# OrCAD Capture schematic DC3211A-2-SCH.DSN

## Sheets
1 PAGE2: size Custom
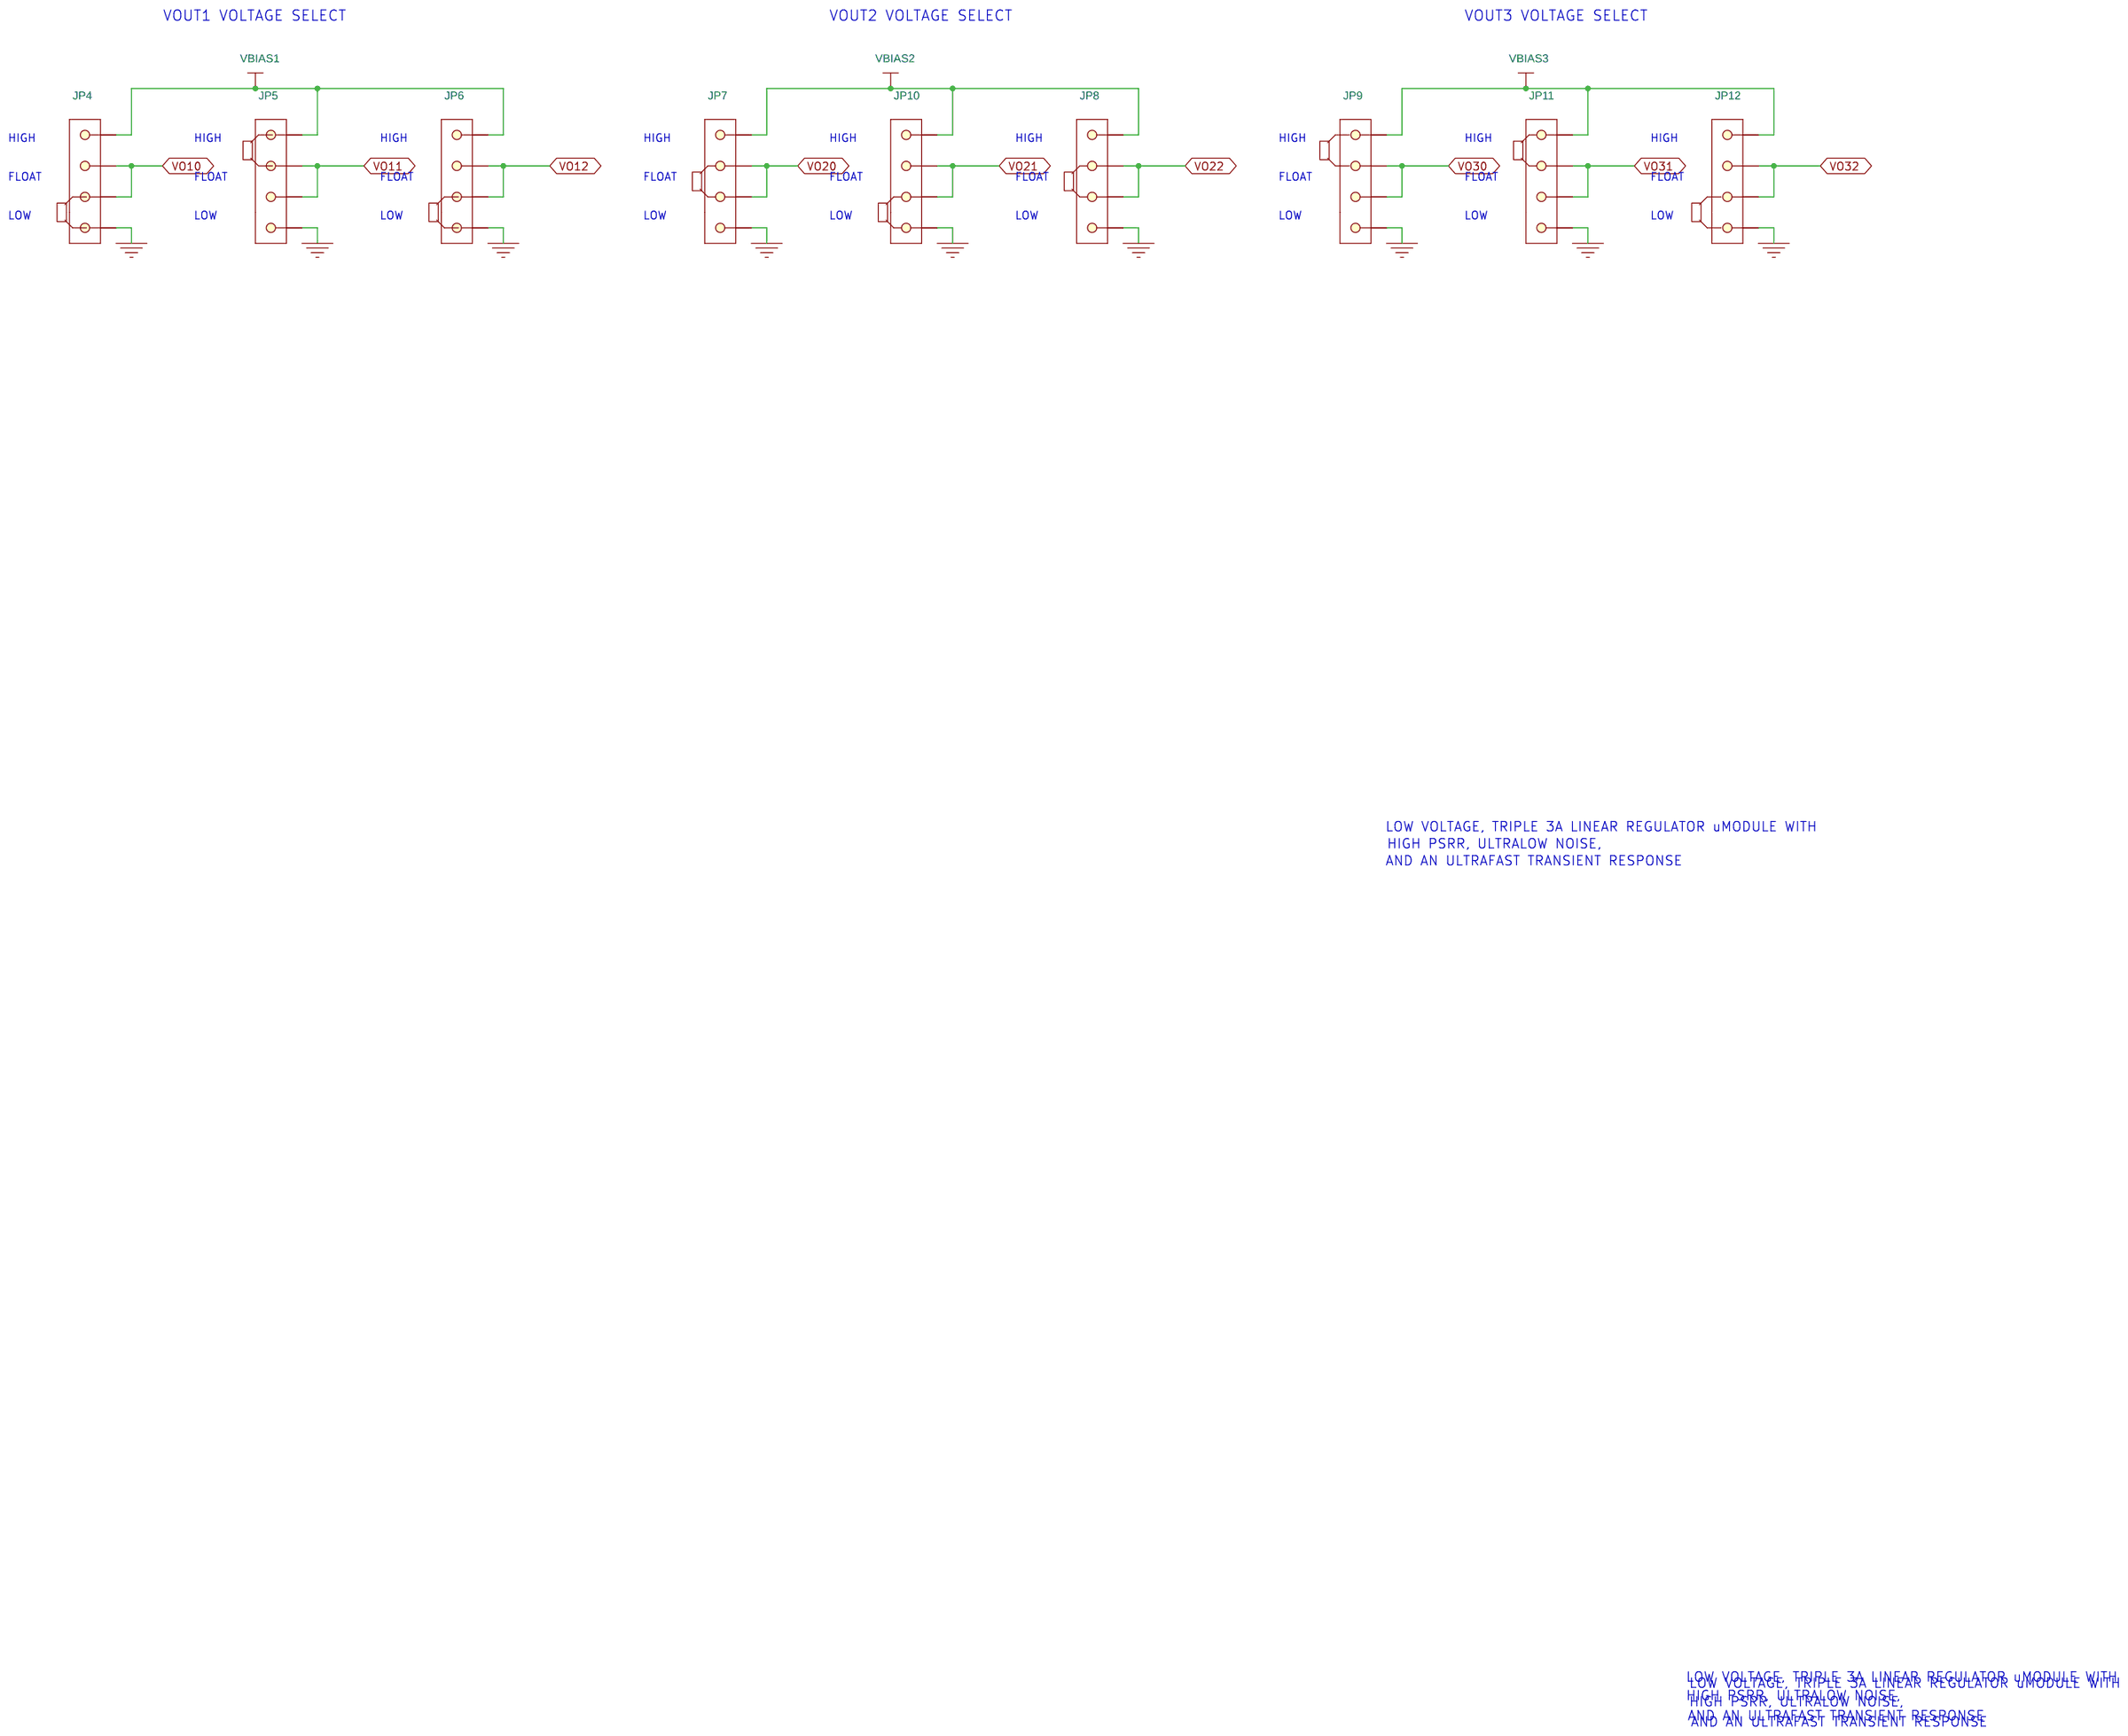
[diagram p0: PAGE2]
2 PAGE1: size Custom
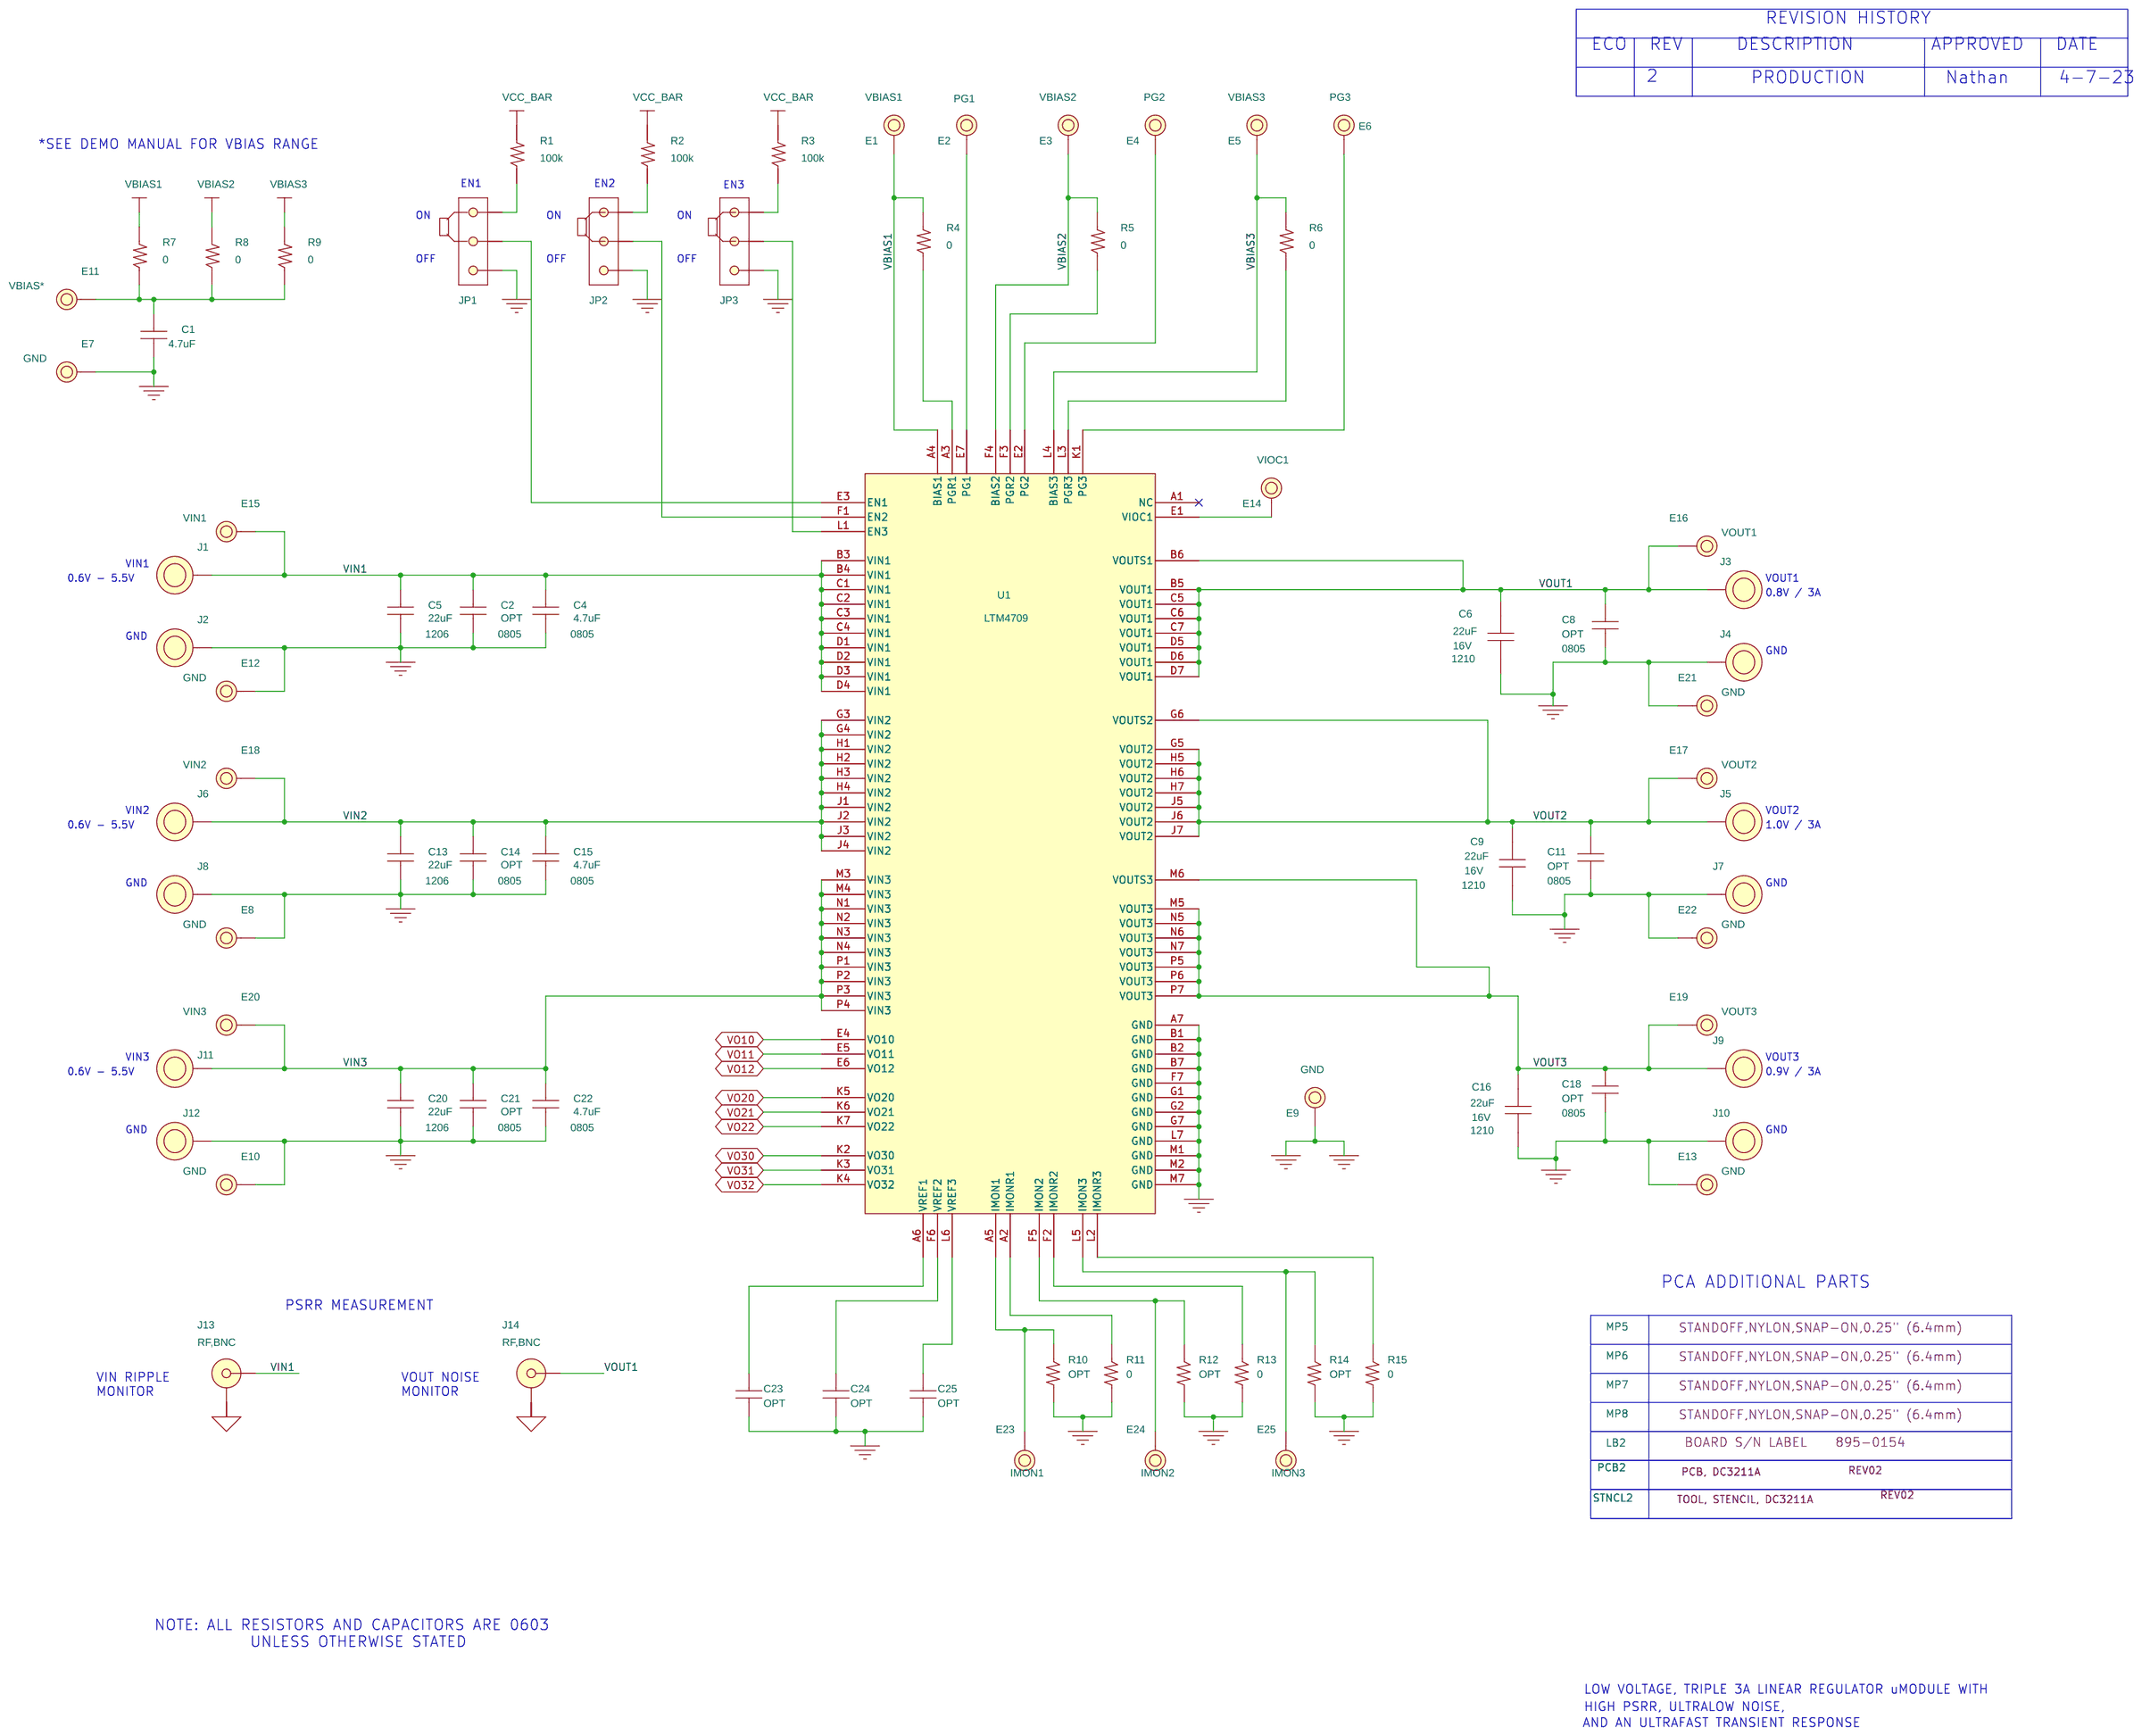
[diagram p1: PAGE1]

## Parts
sheet PAGE1
C1  4.7uF  [CC0603N]
C2  OPT  [CC0805N]
C4  4.7uF  [CC0805N]
C5  22uF  [CC1206N]
C6  22uF  [1210-SP]
C8  OPT  [CC0805N]
C9  22uF  [1210-SP]
C11  OPT  [CC0805N]
C13  22uF  [CC1206N]
C14  OPT  [CC0805N]
C15  4.7uF  [CC0805N]
C16  22uF  [1210-SP]
C18  OPT  [CC0805N]
C20  22uF  [CC1206N]
C21  OPT  [CC0805N]
C22  4.7uF  [CC0805N]
C23  OPT  [CC0603N]
C24  OPT  [CC0603N]
C25  OPT  [CC0603N]
E1  TEST POINT  [MILLMAX2501]
E2  TEST POINT  [MILLMAX2501]
E3  TEST POINT  [MILLMAX2501]
E4  TEST POINT  [MILLMAX2501]
E5  TEST POINT  [MILLMAX2501]
E6  TEST POINT  [MILLMAX2501]
E7  TEST POINT  [MILLMAX2501]
E8  TEST POINT  [MILLMAX2501]
E9  TEST POINT  [MILLMAX2501]
E10  TEST POINT  [MILLMAX2501]
E11  TEST POINT  [MILLMAX2501]
E12  TEST POINT  [MILLMAX2501]
E13  TEST POINT  [MILLMAX2501]
E14  TEST POINT  [MILLMAX2501]
E15  TEST POINT  [MILLMAX2501]
E16  TEST POINT  [MILLMAX2501]
E17  TEST POINT  [MILLMAX2501]
E18  TEST POINT  [MILLMAX2501]
E19  TEST POINT  [MILLMAX2501]
E20  TEST POINT  [MILLMAX2501]
E21  TEST POINT  [MILLMAX2501]
E22  TEST POINT  [MILLMAX2501]
E23  TEST POINT  [MILLMAX2501]
E24  TEST POINT  [MILLMAX2501]
E25  TEST POINT  [MILLMAX2501]
J1  BANANA JACK  [KEY-575-4]
J2  BANANA JACK  [KEY-575-4]
J3  BANANA JACK  [KEY-575-4]
J4  BANANA JACK  [KEY-575-4]
J5  BANANA JACK  [KEY-575-4]
J6  BANANA JACK  [KEY-575-4]
J7  BANANA JACK  [KEY-575-4]
J8  BANANA JACK  [KEY-575-4]
J9  BANANA JACK  [KEY-575-4]
J10  BANANA JACK  [KEY-575-4]
J11  BANANA JACK  [KEY-575-4]
J12  BANANA JACK  [KEY-575-4]
J13  RF,BNC  [CONNEX-112404]
J14  RF,BNC  [CONNEX-112404]
JP1  HDR.  [HD1X3-079]
JP2  HDR.  [HD1X3-079]
JP3  HDR.  [HD1X3-079]
LB2  LABEL  [895-0154_REV01]
MP5  STANDOFF  [MTG-8831]
MP6  STANDOFF  [MTG-8831]
MP7  STANDOFF  [MTG-8831]
MP8  STANDOFF  [MTG-8831]
PCB2  PCB, DC3211A
R1  100k  [CR0603N]
R2  100k  [CR0603N]
R3  100k  [CR0603N]
R4  0  [CR0603N]
R5  0  [CR0603N]
R6  0  [CR0603N]
R7  0  [CR0603N]
R8  0  [CR0603N]
R9  0  [CR0603N]
R10  OPT  [CR0603N]
R11  0  [CR0603N]
R12  OPT  [CR0603N]
R13  0  [CR0603N]
R14  OPT  [CR0603N]
R15  0  [CR0603N]
STNCL2  TOOL, STENCIL, DC3211A
U1  LTM4709  [LTM-BGA-98-7090]
XJP1  SHUNT
XJP2  SHUNT
XJP3  SHUNT
sheet PAGE2
JP4  HDR  [HD1X4-079]
JP5  HDR  [HD1X4-079]
JP6  HDR  [HD1X4-079]
JP7  HDR  [HD1X4-079]
JP8  HDR  [HD1X4-079]
JP9  HDR  [HD1X4-079]
JP10  HDR  [HD1X4-079]
JP11  HDR  [HD1X4-079]
JP12  HDR  [HD1X4-079]
XJP4  SHUNT
XJP5  SHUNT
XJP6  SHUNT
XJP7  SHUNT
XJP8  SHUNT
XJP9  SHUNT
XJP10  SHUNT
XJP11  SHUNT
XJP12  SHUNT

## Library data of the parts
C1 = CAP: CAP.,4.7uF,X5R,16V,10%,0603; CLASS: DISCRETE; Dielectric Type: X5R; FPLIST: CC0603N,CC0603L,CC0603M; Inventory Qty: 44050; Manufacturer: MURATA; Manufacturer PN: GRM188R61C475KAAJD; PART_NUMBER: 150-3182; Package Size: 0603; Rated Voltage: 16V; Tolerance: 10%
C2 C8 C11 C14 C18 C21 = CAP: CAP., OPTION, 0805; CLASS: DISCRETE; FPLIST: CC0805N,CC0805L,CC0805M; PART_NUMBER: 150-3036; Package Size: 0805; Package Type: SMD
C4 C15 C22 = CAP: CAP.,4.7uF,X7R,16V,10%,0805; CLASS: DISCRETE; Dielectric Type: X7R; FPLIST: CC0805N,CC0805L,CC0805M; Inventory Qty: 29963; Manufacturer: AVX; Manufacturer PN: 0805YC475KAT2A; PART_NUMBER: 150-0152; Package Size: 0805; Rated Voltage: 16V; Tolerance: 10%
C5 C13 C20 = CAP: CAP.,22uF,X7R,10V,10%,1206; CLASS: DISCRETE; Dielectric Type: X7R; FPLIST: CC1206N,CC1206L,CC1206M; Inventory Qty: 6204; Manufacturer: MURATA; Manufacturer PN: GRM31CR71A226KE15L; PART_NUMBER: 150-2246; Package Size: 1206; Rated Voltage: 10V; Tolerance: 10%
C6 = CAP_1: CAP.,22uF,X7R,16V,10%,1210,NO SUBS. ALLOWED; CLASS: DISCRETE; Dielectric Type: X7R; FPLIST: CC1206N,CC1206L,CC1206M; Inventory Qty: 12345679; Manufacturer: MURATA; Manufacturer PN: GCM32ER71C226KE19L; PART_NUMBER: LOCAL-150-9876; Package Size: 1210; Rated Voltage: 16V; Tolerance: 10%
C9 = CAP_2: CAP.,22uF,X7R,16V,10%,1210,NO SUBS. ALLOWED; CLASS: DISCRETE; Dielectric Type: X7R; FPLIST: CC1206N,CC1206L,CC1206M; Inventory Qty: 12345679; Manufacturer: MURATA; Manufacturer PN: GCM32ER71C226KE19L; PART_NUMBER: LOCAL-150-9876; Package Size: 1210; Rated Voltage: 16V; Tolerance: 10%
C16 = CAP_3: CAP.,22uF,X7R,16V,10%,1210,NO SUBS. ALLOWED; CLASS: DISCRETE; Dielectric Type: X7R; FPLIST: CC1206N,CC1206L,CC1206M; Inventory Qty: 12345679; Manufacturer: MURATA; Manufacturer PN: GCM32ER71C226KE19L; PART_NUMBER: LOCAL-150-9876; Package Size: 1210; Rated Voltage: 16V; Tolerance: 10%
C23-C25 = CAP: CAP., OPTION, 0603; CLASS: DISCRETE; FPLIST: CC0603N,CC0603L,CC0603M; PART_NUMBER: 150-3038; Package Size: 0603; Package Type: SMD
E1 = TESTPOINT_.219_MILL-MAX_2501: TEST POINT,TURRET,0.094" MTG. HOLE,PCB 0.062" THK; CLASS: IO; Inventory Qty: 823526; Manufacturer: MILL-MAX; Manufacturer PN: 2501-2-00-80-00-00-07-0; PART_FIELD_01: VBIAS1; PART_NUMBER: 260-0003
E2 = TESTPOINT_.219_MILL-MAX_2501: TEST POINT,TURRET,0.094" MTG. HOLE,PCB 0.062" THK; CLASS: IO; Inventory Qty: 823526; Manufacturer: MILL-MAX; Manufacturer PN: 2501-2-00-80-00-00-07-0; PART_FIELD_01: PG1; PART_NUMBER: 260-0003
E3 = TESTPOINT_.219_MILL-MAX_2501: TEST POINT,TURRET,0.094" MTG. HOLE,PCB 0.062" THK; CLASS: IO; Inventory Qty: 823526; Manufacturer: MILL-MAX; Manufacturer PN: 2501-2-00-80-00-00-07-0; PART_FIELD_01: VBIAS2; PART_NUMBER: 260-0003
E4 = TESTPOINT_.219_MILL-MAX_2501: TEST POINT,TURRET,0.094" MTG. HOLE,PCB 0.062" THK; CLASS: IO; Inventory Qty: 823526; Manufacturer: MILL-MAX; Manufacturer PN: 2501-2-00-80-00-00-07-0; PART_FIELD_01: PG2; PART_NUMBER: 260-0003
E5 = TESTPOINT_.219_MILL-MAX_2501: TEST POINT,TURRET,0.094" MTG. HOLE,PCB 0.062" THK; CLASS: IO; Inventory Qty: 823526; Manufacturer: MILL-MAX; Manufacturer PN: 2501-2-00-80-00-00-07-0; PART_FIELD_01: VBIAS3; PART_NUMBER: 260-0003
E6 = TESTPOINT_.219_MILL-MAX_2501: TEST POINT,TURRET,0.094" MTG. HOLE,PCB 0.062" THK; CLASS: IO; Inventory Qty: 823526; Manufacturer: MILL-MAX; Manufacturer PN: 2501-2-00-80-00-00-07-0; PART_FIELD_01: PG3; PART_NUMBER: 260-0003
E7-E10 E12 E13 E21 E22 = TESTPOINT_.219_MILL-MAX_2501: TEST POINT,TURRET,0.094" MTG. HOLE,PCB 0.062" THK; CLASS: IO; Inventory Qty: 823526; Manufacturer: MILL-MAX; Manufacturer PN: 2501-2-00-80-00-00-07-0; PART_FIELD_01: GND; PART_NUMBER: 260-0003
E11 = TESTPOINT_.219_MILL-MAX_2501: TEST POINT,TURRET,0.094" MTG. HOLE,PCB 0.062" THK; CLASS: IO; Inventory Qty: 823526; Manufacturer: MILL-MAX; Manufacturer PN: 2501-2-00-80-00-00-07-0; PART_FIELD_01: VBIAS*; PART_NUMBER: 260-0003
E14 = TESTPOINT_.219_MILL-MAX_2501: TEST POINT,TURRET,0.094" MTG. HOLE,PCB 0.062" THK; CLASS: IO; Inventory Qty: 823526; Manufacturer: MILL-MAX; Manufacturer PN: 2501-2-00-80-00-00-07-0; PART_FIELD_01: VIOC1; PART_NUMBER: 260-0003
E15 = TESTPOINT_.219_MILL-MAX_2501: TEST POINT,TURRET,0.094" MTG. HOLE,PCB 0.062" THK; CLASS: IO; Inventory Qty: 823526; Manufacturer: MILL-MAX; Manufacturer PN: 2501-2-00-80-00-00-07-0; PART_FIELD_01: VIN1; PART_NUMBER: 260-0003
E16 = TESTPOINT_.219_MILL-MAX_2501: TEST POINT,TURRET,0.094" MTG. HOLE,PCB 0.062" THK; CLASS: IO; Inventory Qty: 823526; Manufacturer: MILL-MAX; Manufacturer PN: 2501-2-00-80-00-00-07-0; PART_FIELD_01: VOUT1; PART_NUMBER: 260-0003
E17 = TESTPOINT_.219_MILL-MAX_2501: TEST POINT,TURRET,0.094" MTG. HOLE,PCB 0.062" THK; CLASS: IO; Inventory Qty: 823526; Manufacturer: MILL-MAX; Manufacturer PN: 2501-2-00-80-00-00-07-0; PART_FIELD_01: VOUT2; PART_NUMBER: 260-0003
E18 = TESTPOINT_.219_MILL-MAX_2501: TEST POINT,TURRET,0.094" MTG. HOLE,PCB 0.062" THK; CLASS: IO; Inventory Qty: 823526; Manufacturer: MILL-MAX; Manufacturer PN: 2501-2-00-80-00-00-07-0; PART_FIELD_01: VIN2; PART_NUMBER: 260-0003
E19 = TESTPOINT_.219_MILL-MAX_2501: TEST POINT,TURRET,0.094" MTG. HOLE,PCB 0.062" THK; CLASS: IO; Inventory Qty: 823526; Manufacturer: MILL-MAX; Manufacturer PN: 2501-2-00-80-00-00-07-0; PART_FIELD_01: VOUT3; PART_NUMBER: 260-0003
E20 = TESTPOINT_.219_MILL-MAX_2501: TEST POINT,TURRET,0.094" MTG. HOLE,PCB 0.062" THK; CLASS: IO; Inventory Qty: 823526; Manufacturer: MILL-MAX; Manufacturer PN: 2501-2-00-80-00-00-07-0; PART_FIELD_01: VIN3; PART_NUMBER: 260-0003
E23 = TESTPOINT_.219_MILL-MAX_2501: TEST POINT,TURRET,0.094" MTG. HOLE,PCB 0.062" THK; CLASS: IO; Inventory Qty: 823526; Manufacturer: MILL-MAX; Manufacturer PN: 2501-2-00-80-00-00-07-0; PART_FIELD_01: IMON1; PART_NUMBER: 260-0003
E24 = TESTPOINT_.219_MILL-MAX_2501: TEST POINT,TURRET,0.094" MTG. HOLE,PCB 0.062" THK; CLASS: IO; Inventory Qty: 823526; Manufacturer: MILL-MAX; Manufacturer PN: 2501-2-00-80-00-00-07-0; PART_FIELD_01: IMON2; PART_NUMBER: 260-0003
E25 = TESTPOINT_.219_MILL-MAX_2501: TEST POINT,TURRET,0.094" MTG. HOLE,PCB 0.062" THK; CLASS: IO; Inventory Qty: 823526; Manufacturer: MILL-MAX; Manufacturer PN: 2501-2-00-80-00-00-07-0; PART_FIELD_01: IMON3; PART_NUMBER: 260-0003
J1-J12 = BANANA_KEYSTONE-575-4: CONN.,BANANA JACK,FEMALE,THT,NON-INSULATED,SWAGE,0.218"; CLASS: IO; Inventory Qty: 203061; Manufacturer: KEYSTONE; Manufacturer PN: 575-4; PART_NUMBER: 250-0428
J13 J14 = BNC_50_OHM_112404_B: CONN.,RF,BNC,RCPT,JACK,5-PIN,ST,THT,50 OHMS; CLASS: IO; Inventory Qty: 80023; Manufacturer: AMPHENOL RF; Manufacturer PN: 112404; PART_NUMBER: 250-0427
JP1-JP3 = HDR1X3: CONN.,HDR.,MALE,1x3,2mm,VERT,ST,THT; CLASS: IO; Inventory Qty: 219994; Manufacturer: SULLINS CONNECTOR SOLUTIONS; Manufacturer PN: NRPN031PAEN-RC; PART_NUMBER: 250-0418
LB2 = BLANK_LABEL: LABEL SPEC, DEMO BOARD SERIAL NUMBER; Inventory Qty: 0; Manufacturer: BRADY; Manufacturer PN: THT-96-717-10; PART_FIELD_01: BOARD S/N LABEL; PART_NUMBER: 895-0154
MP5-MP8 = BLANK_MECHANICAL_PART: STANDOFF,NYLON,SNAP-ON,0.25" (6.4mm); CLASS: DISCRETE; Inventory Qty: 227624; Manufacturer: KEYSTONE; Manufacturer PN: 8831; PART_NUMBER: 763-0006
PCB2 = BLANK_PCB_PART: BOM Notes: REV02; CLASS: DISCRETE; Inventory Qty: 0; Manufacturer: ADI APPROVED SUPPLIER; Manufacturer PN: 600-DC3211A; PART_NUMBER: 600-DC3211A
R1-R3 = RES_ALT: RES.,100k OHMS,1%,1/10W,0603; CLASS: DISCRETE; FPLIST: CR0603N,CR0603L,CR0603M; Inventory Qty: 70727; Manufacturer: STACKPOLE ELECTRONICS, INC.; Manufacturer PN: RMCF0603FG100K; PART_NUMBER: 100-0112; Package Size: 0603; Rated Power: 1/10W; Tolerance: 1%
R4-R9 R11 R13 R15 = RES_ALT: RES.,0 OHM,1/10W,0603; CLASS: DISCRETE; FPLIST: CR0603N,CR0603L,CR0603M; Inventory Qty: 57380; Manufacturer: BOURNS; Manufacturer PN: CR0603-J/-000ELF; PART_NUMBER: 100-2621; Package Size: 0603; Rated Power: 1/10W
R10 R12 R14 = RES_ALT: RES., OPTION, 0603; CLASS: DISCRETE; FPLIST: CR0603N,CR0603L,CR0603M; PART_NUMBER: 100-2374; Package Size: 0603
STNCL2 = BLANK_STENCIL_PART: BOM Notes: REV02; CLASS: DISCRETE; Inventory Qty: 0; Manufacturer: ADI APPROVED SUPPLIER; Manufacturer PN: 830-DC3211A; PART_NUMBER: 830-DC3211A
U1 = LTM4709: IC,low  voltaQe, triple 3A linear regulator uModule; CLASS: IC; Inventory Qty: 0; PART_NUMBER: TMP-7406; Package Size: 6mmX12mmX1.92mm; Package Type: linear regulator uModule,BGA-98
XJP1-XJP12 = SHUNT_2MM: CONN.,SHUNT,FEMALE,2 POS,2mm; CLASS: IO; Inventory Qty: 64675; Manufacturer: Wurth Elektronik; Manufacturer PN: 60800213421; PART_NUMBER: 250-0485
JP4-JP12 = HDR1X4: CONN.,HDR,MALE,1x4,2mm,VERT,ST,THT; CLASS: IO; FPLIST: HD1X4-079,JP4X1/079; Inventory Qty: 7912; Manufacturer: SAMTEC; Manufacturer PN: TMM-104-02-L-S; PART_NUMBER: 250-0441

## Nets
GND: C1.2 C2.2 C4.2 C5.2 C6.2 C8.2 C9.2 C11.2 C13.2 C14.2 C15.2 C16.2 C18.2 C20.2 C21.2 C22.2 C23.2 C24.2 C25.2 E7.1 E8.1 E9.1 E10.1 E12.1 E13.1 E21.1 E22.1 J2.1 J4.1 J7.1 J8.1 J10.1 J12.1 J13.2 J13.3 J13.4 J13.5 J14.2 J14.3 J14.4 J14.5 JP1.3 JP2.3 JP3.3 JP4.4 JP5.4 JP6.4 JP7.4 JP8.4 JP9.4 JP10.4 JP11.4 JP12.4 R10.2 R11.2 R12.2 R13.2 R14.2 R15.2 U1.A7(GND) U1.B1(GND) U1.B2(GND) U1.B7(GND) U1.F7(GND) U1.G1(GND) U1.G2(GND) U1.G7(GND) U1.L7(GND) U1.M1(GND) U1.M2(GND) U1.M7(GND)
VIN1: C2.1 C4.1 C5.1 E15.1 J1.1 J13.1 U1.B3(VIN1) U1.B4(VIN1) U1.C1(VIN1) U1.C2(VIN1) U1.C3(VIN1) U1.C4(VIN1) U1.D1(VIN1) U1.D2(VIN1) U1.D3(VIN1) U1.D4(VIN1)
VIN2: C13.1 C14.1 C15.1 E18.1 J6.1 U1.G3(VIN2) U1.G4(VIN2) U1.H1(VIN2) U1.H2(VIN2) U1.H3(VIN2) U1.H4(VIN2) U1.J1(VIN2) U1.J2(VIN2) U1.J3(VIN2) U1.J4(VIN2)
VIN3: C20.1 C21.1 C22.1 E20.1 J11.1 U1.M3(VIN3) U1.M4(VIN3) U1.N1(VIN3) U1.N2(VIN3) U1.N3(VIN3) U1.N4(VIN3) U1.P1(VIN3) U1.P2(VIN3) U1.P3(VIN3) U1.P4(VIN3)
VBIAS1: E1.1 JP4.1 JP5.1 JP6.1 R1.2 R4.2 R7.2 U1.A4(BIAS1)
VBIAS2: E3.1 JP7.1 JP8.1 JP10.1 R2.2 R5.2 R8.2 U1.F4(BIAS2)
VBIAS3: E5.1 JP9.1 JP11.1 JP12.1 R3.2 R6.2 R9.2 U1.L4(BIAS3)
VO10: JP4.2 JP4.3 U1.E4(VO10)
VO11: JP5.2 JP5.3 U1.E5(VO11)
VO12: JP6.2 JP6.3 U1.E6(VO12)
VO20: JP7.2 JP7.3 U1.K5(VO20)
VO21: JP10.2 JP10.3 U1.K6(VO21)
VO22: JP8.2 JP8.3 U1.K7(VO22)
VO30: JP9.2 JP9.3 U1.K2(VO30)
VO31: JP11.2 JP11.3 U1.K3(VO31)
VO32: JP12.2 JP12.3 U1.K4(VO32)
VOUT1: C6.1 C8.1 E16.1 J3.1 J14.1 U1.B5(VOUT1) U1.B6(VOUTS1) U1.C5(VOUT1) U1.C6(VOUT1) U1.C7(VOUT1) U1.D5(VOUT1) U1.D6(VOUT1) U1.D7(VOUT1)
VOUT2: C9.1 C11.1 E17.1 J5.1 U1.G5(VOUT2) U1.G6(VOUTS2) U1.H5(VOUT2) U1.H6(VOUT2) U1.H7(VOUT2) U1.J5(VOUT2) U1.J6(VOUT2) U1.J7(VOUT2)
VOUT3: C16.1 C18.1 E19.1 J9.1 U1.M5(VOUT3) U1.M6(VOUTS3) U1.N5(VOUT3) U1.N6(VOUT3) U1.N7(VOUT3) U1.P5(VOUT3) U1.P6(VOUT3) U1.P7(VOUT3)
N01820: JP2.2 U1.F1(EN2)
N01835: JP1.2 U1.E3(EN1)
N05143: R15.1 U1.L2(IMONR3)
N05158: E25.1 R14.1 U1.L5(IMON3)
N05180: R13.1 U1.F2(IMONR2)
N05202: E24.1 R12.1 U1.F5(IMON2)
N05246: E23.1 R10.1 U1.A5(IMON1)
N16731113: C1.1 E11.1 R7.1 R8.1 R9.1
N16731398: JP1.1 R1.1
N16731435: JP2.1 R2.1
N16731442: JP3.1 R3.1
N16746331: C23.1 U1.A6(VREF1)
N16746338: C24.1 U1.F6(VREF2)
N16746353: C25.1 U1.L6(VREF3)
N16747153: JP3.2 U1.L1(EN3)
N16755783: E2.1 U1.E7(PG1)
N16755859: R6.1 U1.L3(PGR3)
N16755871: E6.1 U1.K1(PG3)
N16755976: E4.1 U1.E2(PG2)
N16825035: R11.1 U1.A2(IMONR1)
N16826866: E14.1 U1.E1(VIOC1)
N16827131: R5.1 U1.F3(PGR2)
N16854971: R4.1 U1.A3(PGR1)

Not connected (* = marked no-connect by the designer): U1 A1(NC)*

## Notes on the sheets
sheet 1
- VOUT1 VOLTAGE SELECT
- VOUT2 VOLTAGE SELECT
- VOUT3 VOLTAGE SELECT
- HIGH
- HIGH
- HIGH
- HIGH
- HIGH
- HIGH
- HIGH
- HIGH
- HIGH
- FLOAT
- FLOAT
- FLOAT
- FLOAT
- FLOAT
- FLOAT
- FLOAT
- FLOAT
- FLOAT
- LOW
- LOW
- LOW
- LOW
- LOW
- LOW
- LOW
- LOW
- LOW
- LOW VOLTAGE, TRIPLE 3A LINEAR REGULATOR uMODULE WITH
- HIGH PSRR, ULTRALOW NOISE,
- AND AN ULTRAFAST TRANSIENT RESPONSE
- LOW VOLTAGE, TRIPLE 3A LINEAR REGULATOR uMODULE WITH
- LOW VOLTAGE, TRIPLE 3A LINEAR REGULATOR uMODULE WITH
- HIGH PSRR, ULTRALOW NOISE,
- HIGH PSRR, ULTRALOW NOISE,
- AND AN ULTRAFAST TRANSIENT RESPONSE
- AND AN ULTRAFAST TRANSIENT RESPONSE
sheet 2
- REVISION HISTORY
- ECO
- REV
- DESCRIPTION
- APPROVED
- DATE
- 2
- PRODUCTION
- Nathan
- 4-7-23
- *SEE DEMO MANUAL FOR VBIAS RANGE
- EN1
- EN2
- EN3
- ON
- ON
- ON
- OFF
- OFF
- OFF
- VIN1
- 0.6V - 5.5V
- VOUT1
- 0.8V / 3A
- GND
- GND
- 0.6V - 5.5V
- VIN2
- 1.0V / 3A
- VOUT2
- GND
- GND
- VIN3
- VOUT3
- 0.6V - 5.5V
- 0.9V / 3A
- GND
- GND
- PCA ADDITIONAL PARTS
- PSRR MEASUREMENT
- VIN RIPPLE
  MONITOR
- VOUT NOISE
  MONITOR
- NOTE: ALL RESISTORS AND CAPACITORS ARE 0603
              UNLESS OTHERWISE STATED
- LOW VOLTAGE, TRIPLE 3A LINEAR REGULATOR uMODULE WITH
- HIGH PSRR, ULTRALOW NOISE,
- AND AN ULTRAFAST TRANSIENT RESPONSE
